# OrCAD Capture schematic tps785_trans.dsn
size A
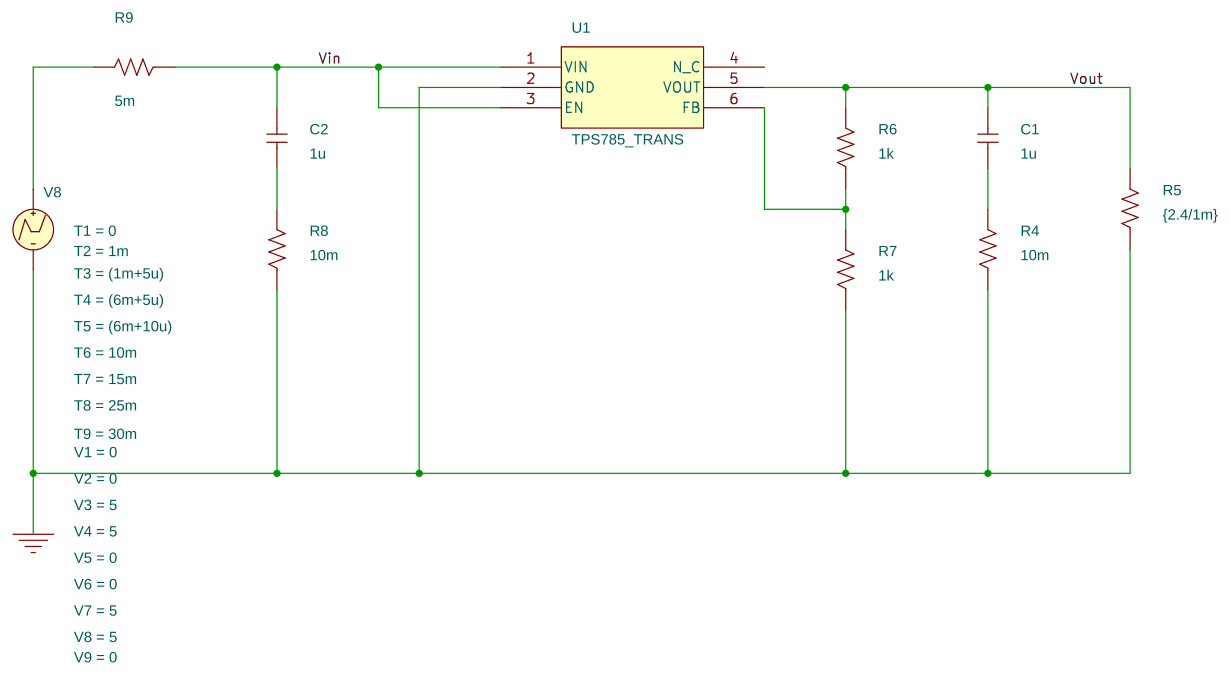
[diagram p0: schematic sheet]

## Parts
C1  1u  [cap196]
C2  1u  [cap196]
R4  10m  [AXRC05]
R5  {2.4/1m}  [AXRC05]
R6  1k  [AXRC05]
R7  1k  [AXRC05]
R8  10m  [AXRC05]
R9  5m  [AXRC05]
U1  TPS785_TRANS
V8  VPWL

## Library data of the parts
C1 C2 = C
R4-R9 = R
U1 = TPS785_TRANS
V8 = VPWL: T1: 0; T2: 1m; T3: (1m+5u); T4: (6m+5u); T5: (6m+10u); T6: 10m; T7: 15m; T8: 25m; T9: 30m; V1: 0; V2: 0; V3: 5; V4: 5; V5: 0; V6: 0; V7: 5; V8: 5; V9: 0

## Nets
Vin: C2.2 R9.1 U1.1(VIN) U1.3(EN)
0: R4.1 R5.1 R7.1 R8.1 U1.2(GND) V8.2(-)
Vout: C1.2 R5.2 R6.2 U1.5(VOUT)
N00233: R9.2 V8.1(+)
N00391: C1.1 R4.2
N05253: R6.1 R7.2 U1.6(FB)
N05361: C2.1 R8.2

Not connected (* = marked no-connect by the designer): U1 4(N_C)
